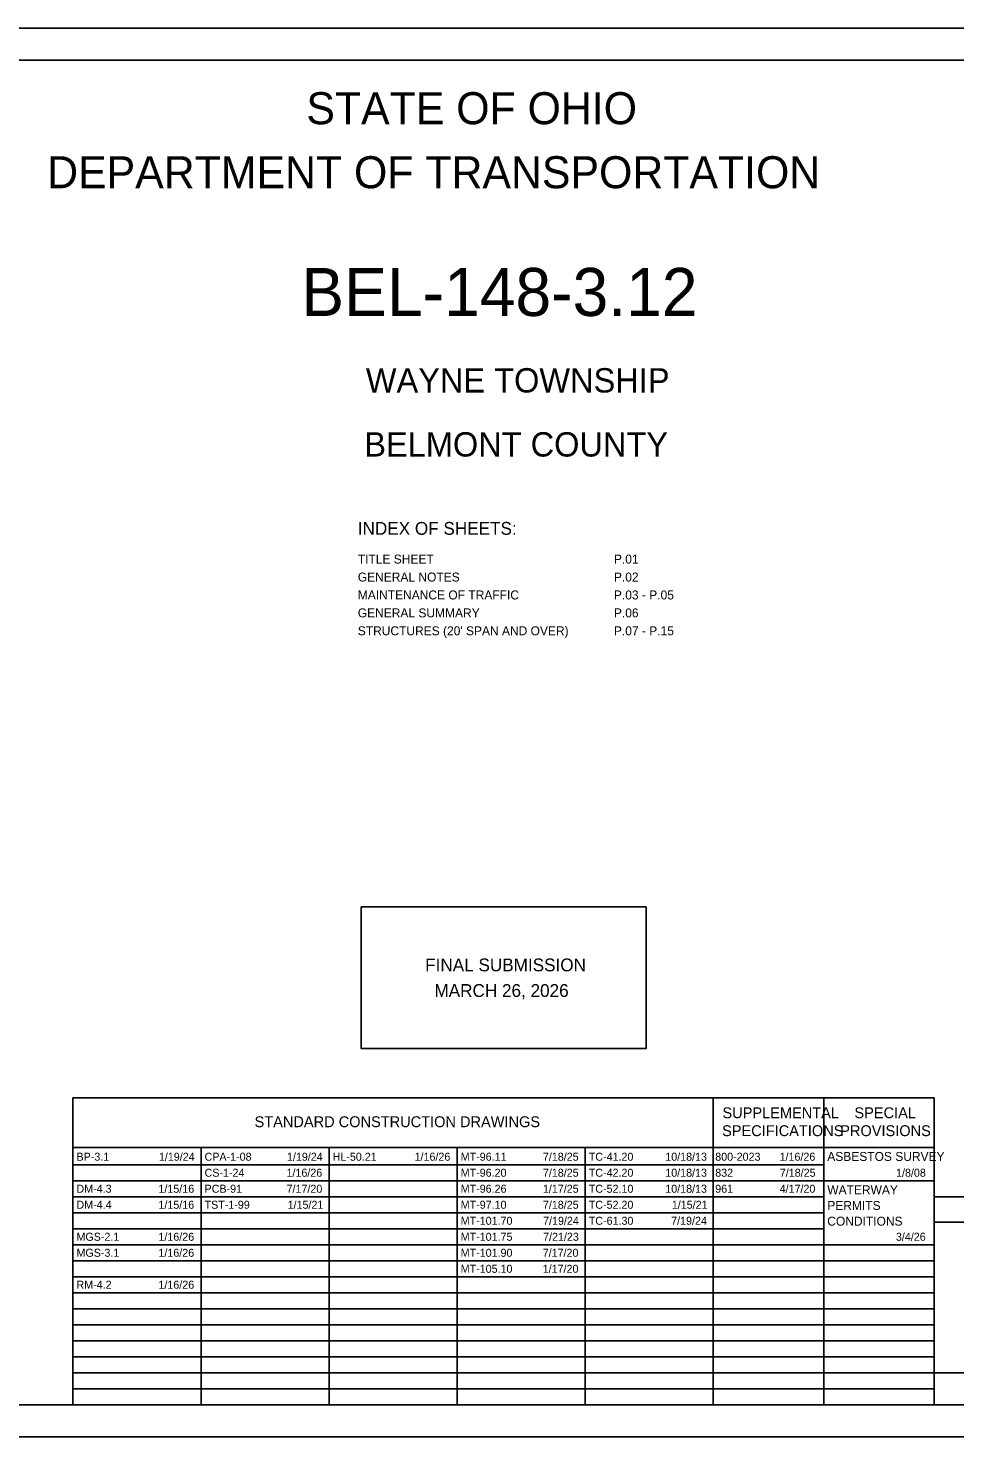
# Model space of a CAD drawing. Extents: x -7.9 to 76.1, y 0 to 22.
# Drawn here: x 9.45 to 23.92, y 0 to 22 of the extents above; entities that cross this region are included whole.
import ezdxf

# ---------------------------------------------------------------- set-up
doc = ezdxf.new("R2010")
doc.units = 0
for name, color, linetype in [('SH_Border', 7, 'Continuous'), ('SH_Cut_Line', 7, 'Continuous'), ('SH_Data', 7, 'Continuous'), ('SH_Text', 7, 'Continuous')]:
    doc.layers.add(name, color=color, linetype=linetype)

msp = doc.modelspace()

# ---------------------------------------------------------------- linework, layer by layer
at = {"layer": 'SH_Border'}
for points in [[(1.5, 21.5), (33.5, 21.5), (33.5, 0.5), (1.5, 0.5)], [(14.651, 8.277), (19.099, 8.277), (19.099, 6.063), (14.651, 6.063)]]:
    msp.add_lwpolyline(points, close=True, dxfattribs=at)
at = {"layer": 'SH_Cut_Line'}
msp.add_lwpolyline([(0, 0), (34, 0), (34, 22), (0, 22)], close=True, dxfattribs=at)
at = {"layer": 'SH_Data'}
for p, q in [((10.15, 5.292), (23.6, 5.292)), ((10.15, 0.5), (10.15, 5.292)), ((20.15, 0.5), (20.15, 5.292)), ((21.875, 0.5), (21.875, 5.292)), ((23.6, 0.5), (23.6, 5.292)), ((10.15, 4.521), (23.6, 4.521)), ((12.15, 0.5), (12.15, 4.521)), ((14.15, 0.5), (14.15, 4.521)), ((16.15, 0.5), (16.15, 4.521)), ((18.15, 0.5), (18.15, 4.521)), ((10.15, 4.25), (21.875, 4.25)), ((10.15, 4), (23.6, 4)), ((10.15, 3.75), (21.875, 3.75)), ((23.6, 0.5), (23.6, 3.75)), ((23.6, 3.75), (26.4, 3.75)), ((10.15, 3.5), (21.875, 3.5)), ((23.6, 3.35), (26.4, 3.35)), ((10.15, 3.25), (21.875, 3.25)), ((10.15, 3), (23.6, 3)), ((10.15, 2.75), (23.6, 2.75)), ((10.15, 2.5), (23.6, 2.5)), ((10.15, 2.25), (23.6, 2.25)), ((10.15, 2), (23.6, 2)), ((10.15, 1.75), (23.6, 1.75)), ((10.15, 1.5), (23.6, 1.5)), ((10.15, 1.25), (23.6, 1.25)), ((10.15, 1), (23.6, 1)), ((10.15, 0.75), (23.6, 0.75)), ((23.6, 0.5), (26.4, 0.5))]:
    msp.add_line(p, q, dxfattribs=at)
msp.add_lwpolyline([(23.6, 0.5), (23.6, 1), (26.4, 1), (26.4, 0.5)], close=True, dxfattribs=at)

# ---------------------------------------------------------------- texts
at = {"layer": 'SH_Border'}
for s, p in [('FINAL SUBMISSION', (15.65, 7.27)), ('MARCH 26, 2026', (15.795, 6.87))]:
    msp.add_text(s, height=0.2, dxfattribs=at).set_placement(p)
at = {"layer": 'SH_Text'}
for s, height, p in [('STATE OF OHIO', 0.5, (13.795, 20.5)), ('DEPARTMENT OF TRANSPORTATION', 0.5, (9.747, 19.5)), ('BEL-148-3.12', 0.75, (13.715, 17.505)), ('   WAYNE TOWNSHIP   ', 0.38, (14.3, 16.31)), ('   BELMONT COUNTY   ', 0.38, (14.276, 15.31)), ('INDEX OF SHEETS:', 0.2, (14.598, 14.088)), ('TITLE SHEET', 0.14, (14.598, 13.638)), ('P.01', 0.14, (18.598, 13.638)), ('GENERAL NOTES', 0.14, (14.598, 13.358)), ('P.02', 0.14, (18.598, 13.358)), ('MAINTENANCE OF TRAFFIC', 0.14, (14.598, 13.078)), ('P.03 - P.05', 0.14, (18.598, 13.078)), ('GENERAL SUMMARY', 0.14, (14.598, 12.798)), ('P.06', 0.14, (18.598, 12.798)), ("STRUCTURES (20' SPAN AND OVER)", 0.14, (14.598, 12.518)), ('P.07 - P.15', 0.14, (18.598, 12.518)), ('SUPPLEMENTAL', 0.17, (20.293, 4.976)), ('SPECIAL', 0.17, (22.354, 4.976)), ('STANDARD CONSTRUCTION DRAWINGS', 0.17, (12.986, 4.836)), ('SPECIFICATIONS', 0.17, (20.287, 4.696)), ('PROVISIONS', 0.17, (22.132, 4.696)), ('BP-3.1', 0.125, (10.205, 4.312)), ('1/19/24', 0.125, (11.492, 4.312)), ('CPA-1-08', 0.125, (12.205, 4.312)), ('1/19/24', 0.125, (13.492, 4.312)), ('HL-50.21', 0.125, (14.205, 4.312)), ('1/16/26', 0.125, (15.485, 4.312)), ('MT-96.11', 0.125, (16.205, 4.312)), ('7/18/25', 0.125, (17.489, 4.312)), ('TC-41.20', 0.125, (18.205, 4.312)), ('10/18/13', 0.125, (19.4, 4.312)), ('800-2023', 0.125, (20.18, 4.312)), ('1/16/26', 0.125, (21.185, 4.312)), ('ASBESTOS SURVEY', 0.14, (21.93, 4.309)), ('CS-1-24', 0.125, (12.205, 4.062)), ('1/16/26', 0.125, (13.485, 4.062)), ('MT-96.20', 0.125, (16.205, 4.062)), ('7/18/25', 0.125, (17.489, 4.062)), ('TC-42.20', 0.125, (18.205, 4.062)), ('10/18/13', 0.125, (19.4, 4.062)), ('832', 0.125, (20.18, 4.062)), ('7/18/25', 0.125, (21.189, 4.062)), ('1/8/08', 0.125, (23.004, 4.062)), ('DM-4.3', 0.125, (10.205, 3.812)), ('1/15/16', 0.125, (11.485, 3.812)), ('PCB-91', 0.125, (12.205, 3.812)), ('7/17/20', 0.125, (13.486, 3.812)), ('MT-96.26', 0.125, (16.205, 3.812)), ('1/17/25', 0.125, (17.489, 3.812)), ('TC-52.10', 0.125, (18.205, 3.812)), ('10/18/13', 0.125, (19.4, 3.812)), ('961', 0.125, (20.18, 3.812)), ('4/17/20', 0.125, (21.186, 3.812)), ('WATERWAY ', 0.14, (21.93, 3.788)), ('DM-4.4', 0.125, (10.205, 3.562)), ('1/15/16', 0.125, (11.485, 3.562)), ('TST-1-99', 0.125, (12.205, 3.562)), ('1/15/21', 0.125, (13.502, 3.562)), ('MT-97.10', 0.125, (16.205, 3.562)), ('7/18/25', 0.125, (17.489, 3.562)), ('TC-52.20', 0.125, (18.205, 3.562)), ('1/15/21', 0.125, (19.502, 3.562)), ('PERMITS', 0.14, (21.93, 3.543)), ('MT-101.70', 0.125, (16.205, 3.312)), ('7/19/24', 0.125, (17.492, 3.312)), ('TC-61.30', 0.125, (18.205, 3.312)), ('7/19/24', 0.125, (19.492, 3.312)), ('CONDITIONS', 0.14, (21.93, 3.298)), ('MGS-2.1', 0.125, (10.205, 3.062)), ('1/16/26', 0.125, (11.485, 3.062)), ('MT-101.75', 0.125, (16.205, 3.062)), ('7/21/23', 0.125, (17.492, 3.062)), ('3/4/26', 0.125, (23.002, 3.062)), ('MGS-3.1', 0.125, (10.205, 2.812)), ('1/16/26', 0.125, (11.485, 2.812)), ('MT-101.90', 0.125, (16.205, 2.812)), ('7/17/20', 0.125, (17.486, 2.812)), ('MT-105.10', 0.125, (16.205, 2.562)), ('1/17/20', 0.125, (17.486, 2.562)), ('RM-4.2', 0.125, (10.205, 2.313)), ('1/16/26', 0.125, (11.485, 2.313))]:
    msp.add_text(s, height=height, dxfattribs=at).set_placement(p)

doc.saveas('drawing.dxf')
